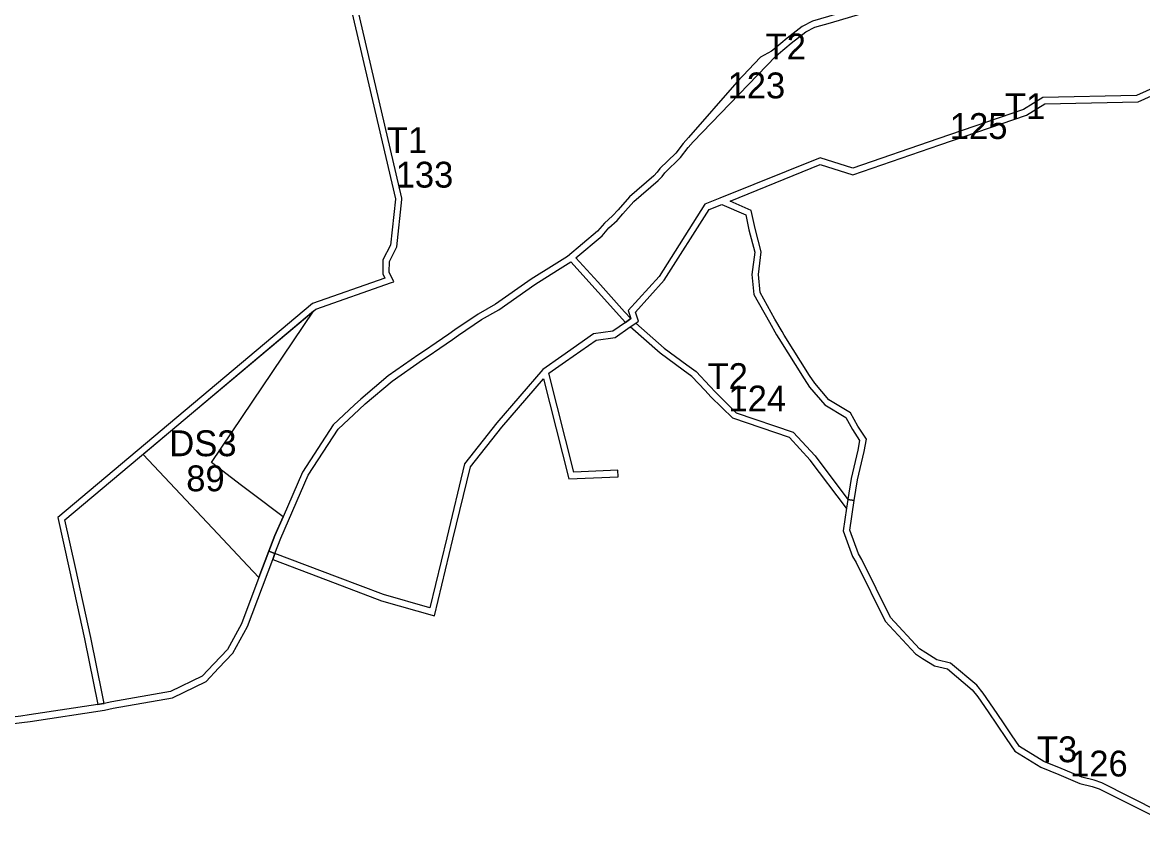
# Model space of a CAD drawing. Extents: x -477001 to -465642, y -1158278 to -1150672.
# Drawn here: x -469997 to -469477, y -1153800 to -1153423 of the extents above; entities that cross this region are included whole.
import ezdxf

# ---------------------------------------------------------------- set-up
doc = ezdxf.new("R2010")
doc.units = 0
for name, color, linetype in [('VPS_id', 7, 'Continuous'), ('VPS_n', 7, 'Continuous'), ('vyvlastneni_n', 7, 'Continuous')]:
    doc.layers.add(name, color=color, linetype=linetype)

msp = doc.modelspace()

# ---------------------------------------------------------------- linework, layer by layer
at = {"layer": 'VPS_n'}
for p, q in [((-469649.29, -1153436.68), (-469654.43, -1153439.34)), ((-469572.05, -1153477.33), (-469611.58, -1153490.89)), ((-469698.89, -1153493.04), (-469691.53, -1153485.91)), ((-469668.56, -1153506.2), (-469626.63, -1153489.26)), ((-469626.63, -1153489.26), (-469611.54, -1153494.04)), ((-469672.44, -1153507.77), (-469661.29, -1153512.67)), ((-469740.12, -1153532.5), (-469728, -1153522.3)), ((-469742.44, -1153534.42), (-469717.12, -1153562.51)), ((-469861.91, -1153557.27), (-469941.15, -1153623.82)), ((-469711.11, -1153561.96), (-469712.43, -1153557.85)), ((-469721.93, -1153569.54), (-469714.91, -1153564.62)), ((-469717.12, -1153562.51), (-469714.64, -1153560.78)), ((-469714.91, -1153564.62), (-469712.38, -1153562.85)), ((-469712.38, -1153562.85), (-469711.11, -1153561.96)), ((-469730.79, -1153570.76), (-469721.93, -1153569.54)), ((-469645.88, -1153570.06), (-469634.12, -1153588.78)), ((-469746.7, -1153578.23), (-469755.5, -1153584.39)), ((-469755.5, -1153584.39), (-469776.88, -1153609.23)), ((-469755.23, -1153588.67), (-469743.37, -1153635.1)), ((-469741.06, -1153632), (-469752.78, -1153586.14)), ((-469634.12, -1153588.78), (-469631.59, -1153592.55)), ((-469631.59, -1153592.55), (-469624.59, -1153600.78)), ((-469624.59, -1153600.78), (-469614.84, -1153606.66)), ((-469612.61, -1153604.5), (-469622.62, -1153598.46)), ((-469614.84, -1153606.66), (-469611.75, -1153612.19)), ((-469776.88, -1153609.23), (-469791.81, -1153628.18)), ((-469609.17, -1153621.89), (-469612.36, -1153635)), ((-469941.15, -1153623.82), (-469908.95, -1153658.04)), ((-469609.41, -1153635.58), (-469606.23, -1153622.5)), ((-469791.81, -1153628.18), (-469800.13, -1153662.51)), ((-469797.21, -1153663.22), (-469789.05, -1153629.52)), ((-469743.37, -1153635.1), (-469720.57, -1153634.19)), ((-469612.36, -1153635), (-469613.82, -1153644.71)), ((-469610.85, -1153645.16), (-469609.41, -1153635.58)), ((-469885.46, -1153645.71), (-469895.39, -1153638.21)), ((-469881.57, -1153648.65), (-469885.46, -1153645.71)), ((-469613.82, -1153644.71), (-469614.45, -1153648.86)), ((-469613.82, -1153644.71), (-469614.45, -1153648.86)), ((-469613.82, -1153644.71), (-469610.85, -1153645.16)), ((-469610.85, -1153645.16), (-469613.82, -1153644.71)), ((-469612.94, -1153659), (-469610.85, -1153645.16)), ((-469876.12, -1153652.76), (-469881.57, -1153648.65)), ((-469614.45, -1153648.86), (-469616.02, -1153659.31)), ((-469908.95, -1153658.04), (-469892.51, -1153675.5)), ((-469800.13, -1153662.51), (-469808.01, -1153695.03)), ((-469616.02, -1153659.31), (-469611.66, -1153671.22)), ((-469608.93, -1153669.95), (-469612.94, -1153659)), ((-469887.31, -1153681.03), (-469882.68, -1153668.8)), ((-469879.88, -1153669.86), (-469882.68, -1153668.8)), ((-469882.68, -1153668.8), (-469879.88, -1153669.86)), ((-469880.94, -1153672.67), (-469879.88, -1153669.86)), ((-469879.88, -1153669.86), (-469880.94, -1153672.67)), ((-469850.88, -1153680.84), (-469879.88, -1153669.86)), ((-469607.39, -1153672.66), (-469608.93, -1153669.95)), ((-469892.51, -1153675.5), (-469887.31, -1153681.03)), ((-469829.53, -1153688.92), (-469850.88, -1153680.84)), ((-469808.01, -1153695.03), (-469829.53, -1153688.92)), ((-469572.52, -1153719.17), (-469577.58, -1153716.01)), ((-469551.03, -1153734.63), (-469553.92, -1153730.99)), ((-469556.08, -1153733.09), (-469553.45, -1153736.41)), ((-469553.45, -1153736.41), (-469548.74, -1153743.32)), ((-469524.28, -1153769.01), (-469515.91, -1153772.5)), ((-469497.07, -1153779.12), (-469455.84, -1153799.88))]:
    msp.add_line(p, q, dxfattribs=at)
for points in [[(-469924.03, -1153225.48), (-469924.14, -1153237.9), (-469924.24, -1153248.64), (-469933.25, -1153282.8), (-469932.94, -1153293.65), (-469928.03, -1153316.16), (-469917.44, -1153355.79), (-469900.76, -1153373.26), (-469882.11, -1153382.51), (-469868.23, -1153389.4), (-469848.65, -1153399.12), (-469823.97, -1153505.24), (-469823.97, -1153505.33), (-469826.25, -1153526.64), (-469829.73, -1153533.5), (-469829.85, -1153539.94), (-469828.88, -1153541.96), (-469862.41, -1153553.77), (-469980.74, -1153653.15), (-469975.5, -1153676.95), (-469968.34, -1153709.45), (-469962.14, -1153739.93)], [(-469434.21, -1153343.98), (-469486.99, -1153367.69), (-469533.66, -1153388.67), (-469567.53, -1153403.78), (-469575.25, -1153407.62), (-469580.07, -1153409.16), (-469591.53, -1153411.76), (-469594.27, -1153412.12), (-469604.55, -1153415.16), (-469622.77, -1153420.54), (-469630.33, -1153422.61), (-469635.05, -1153425.16), (-469641.99, -1153430.58), (-469647.94, -1153435.55), (-469649.29, -1153436.68)], [(-469691.53, -1153485.91), (-469687.93, -1153481.41), (-469685.68, -1153478.75), (-469647.24, -1153438.88), (-469646.02, -1153437.85), (-469640.1, -1153432.91), (-469633.4, -1153427.68), (-469629.21, -1153425.41), (-469621.95, -1153423.43), (-469603.7, -1153418.04), (-469593.65, -1153415.06), (-469591, -1153414.72), (-469579.28, -1153412.06), (-469574.12, -1153410.41), (-469566.25, -1153406.49), (-469532.43, -1153391.41), (-469485.76, -1153370.43), (-469433.06, -1153346.75)], [(-469959.17, -1153739.45), (-469959.96, -1153735.58), (-469965.41, -1153708.83), (-469972.57, -1153676.31), (-469977.42, -1153654.27), (-469860.9, -1153556.42), (-469825.83, -1153544.07), (-469824.72, -1153543.68), (-469826.84, -1153539.28), (-469826.74, -1153534.24), (-469823.33, -1153527.51), (-469820.97, -1153505.51), (-469820.96, -1153504.92), (-469845.73, -1153398.41)], [(-469654.43, -1153439.34), (-469665.41, -1153451.06), (-469687.91, -1153476.74)], [(-469530.93, -1153466.4), (-469522.38, -1153461.1), (-469479.09, -1153460.16), (-469433.64, -1153439.78)], [(-469437.42, -1153438.18), (-469479.76, -1153457.17), (-469523.26, -1153458.12)], [(-469523.26, -1153458.12), (-469532.23, -1153463.67), (-469572.05, -1153477.33)], [(-469611.54, -1153494.04), (-469571.08, -1153480.17), (-469530.93, -1153466.4)], [(-469687.91, -1153476.74), (-469690.25, -1153479.5), (-469693.76, -1153483.89), (-469701.2, -1153491.11)], [(-469611.58, -1153490.89), (-469626.75, -1153486.08), (-469673.29, -1153504.87)], [(-469701.2, -1153491.11), (-469702.37, -1153492.85), (-469703.94, -1153494.48), (-469715.27, -1153504.3), (-469720.54, -1153510.21), (-469723.07, -1153513.06), (-469726.93, -1153516.52), (-469730.11, -1153520.15), (-469744.05, -1153531.89), (-469750.24, -1153535.79), (-469760.9, -1153542.49), (-469777.54, -1153554.12), (-469785.56, -1153558.69), (-469796.36, -1153566.04), (-469799.16, -1153567.94), (-469804.99, -1153571.96), (-469810.5, -1153575.75), (-469813.03, -1153577.5), (-469827.27, -1153587.39), (-469840.03, -1153598.14), (-469842.89, -1153600.81), (-469852.84, -1153610.11), (-469867.1, -1153632.03), (-469876.12, -1153652.76), (-469879.93, -1153661.52), (-469882.68, -1153668.8)], [(-469728, -1153522.3), (-469724.79, -1153518.63), (-469720.94, -1153515.18), (-469718.3, -1153512.2), (-469713.16, -1153506.44), (-469701.87, -1153496.66), (-469700.03, -1153494.74), (-469698.89, -1153493.04)], [(-469673.29, -1153504.87), (-469680.21, -1153507.67), (-469701.46, -1153541.16), (-469715.83, -1153557.09), (-469714.64, -1153560.78), (-469717.12, -1153562.51), (-469723.06, -1153566.66), (-469731.91, -1153567.88), (-469746.7, -1153578.23)], [(-469712.43, -1153557.85), (-469699.08, -1153543), (-469678.19, -1153510.09), (-469672.44, -1153507.77)], [(-469655.38, -1153540.33), (-469654.06, -1153529.73), (-469656.89, -1153518.94), (-469658.68, -1153510.54), (-469668.56, -1153506.2)], [(-469661.29, -1153512.67), (-469659.81, -1153519.63), (-469657.11, -1153529.93), (-469658.4, -1153540.3), (-469657.45, -1153549.65), (-469650.3, -1153562.44)], [(-469714.64, -1153560.78), (-469717.51, -1153557.59), (-469730, -1153543.73), (-469740.12, -1153532.5)], [(-469879.88, -1153669.86), (-469877.15, -1153662.65), (-469864.45, -1153633.46), (-469850.52, -1153612.05), (-469840.84, -1153603), (-469838.04, -1153600.39), (-469825.44, -1153589.77), (-469811.32, -1153579.97), (-469808.8, -1153578.22), (-469803.29, -1153574.43), (-469797.47, -1153570.42), (-469794.67, -1153568.52), (-469783.97, -1153561.24), (-469775.93, -1153556.66), (-469759.24, -1153544.99), (-469748.64, -1153538.33), (-469742.44, -1153534.42)], [(-469647.68, -1153560.97), (-469654.53, -1153548.73), (-469655.38, -1153540.33)], [(-469895.39, -1153638.21), (-469909.36, -1153627.65), (-469861.91, -1153557.27)], [(-469714.91, -1153564.62), (-469712.38, -1153562.85), (-469699.12, -1153574.55), (-469688.6, -1153582.22), (-469684.29, -1153585.35), (-469677.99, -1153592.12), (-469675.35, -1153594.94), (-469665.67, -1153604.45), (-469639.22, -1153613.46), (-469629.05, -1153624.54), (-469613.82, -1153644.71)], [(-469614.45, -1153648.86), (-469631.36, -1153626.46), (-469640.91, -1153616.05), (-469667.28, -1153607.07), (-469677.5, -1153597.04), (-469680.18, -1153594.17), (-469686.29, -1153587.61), (-469690.37, -1153584.64), (-469701, -1153576.89), (-469714.91, -1153564.62)], [(-469650.3, -1153562.44), (-469646.98, -1153568.35), (-469645.88, -1153570.06)], [(-469631.6, -1153587.15), (-469643.35, -1153568.45), (-469644.41, -1153566.8), (-469647.68, -1153560.97)], [(-469752.78, -1153586.14), (-469744.98, -1153580.69), (-469730.79, -1153570.76)], [(-469789.05, -1153629.52), (-469774.56, -1153611.14), (-469755.23, -1153588.67)], [(-469622.62, -1153598.46), (-469629.19, -1153590.74), (-469631.6, -1153587.15)], [(-469606.23, -1153622.5), (-469605.25, -1153616.7), (-469609.18, -1153610.64), (-469612.61, -1153604.5)], [(-469611.75, -1153612.19), (-469608.4, -1153617.35), (-469609.17, -1153621.89)], [(-469720.57, -1153634.19), (-469720.69, -1153631.19), (-469741.06, -1153632)], [(-469882.68, -1153668.8), (-469879.93, -1153661.52), (-469876.12, -1153652.76)], [(-469880.94, -1153672.67), (-469851.94, -1153683.65), (-469830.47, -1153691.77), (-469805.82, -1153698.77), (-469797.21, -1153663.22)], [(-469882.68, -1153668.8), (-469887.31, -1153681.03), (-469895.41, -1153702.45), (-469901.92, -1153714.36), (-469908.25, -1153721.08), (-469913.7, -1153726.86), (-469928.34, -1153733.94), (-469955.61, -1153738.69), (-469959.17, -1153739.45)], [(-470144.94, -1153792.24), (-470140.23, -1153791.32), (-470129.3, -1153787.64), (-470115.74, -1153783.08), (-470108.03, -1153780.1), (-470091.01, -1153773.14), (-470070.47, -1153764.33), (-470057.45, -1153759.75), (-470035.04, -1153753.64), (-470031.12, -1153752.97), (-470015.72, -1153750.56), (-469997.47, -1153748.33), (-469993.57, -1153747.76), (-469959.11, -1153742.5), (-469955.04, -1153741.64), (-469927.41, -1153736.82), (-469911.9, -1153729.32), (-469906.07, -1153723.14), (-469899.47, -1153716.14), (-469892.68, -1153703.71), (-469880.94, -1153672.67)], [(-469611.66, -1153671.22), (-469610.04, -1153674.07), (-469596.54, -1153701.21), (-469582.45, -1153716.49)], [(-469577.58, -1153716.01), (-469580.51, -1153714.16), (-469594.04, -1153699.49), (-469607.39, -1153672.66)], [(-469582.45, -1153716.49), (-469579.18, -1153718.55), (-469573.69, -1153721.97), (-469567.54, -1153723.44), (-469556.08, -1153733.09)], [(-469553.92, -1153730.99), (-469566.15, -1153720.69), (-469572.52, -1153719.17)], [(-469541.89, -1153748.05), (-469546.26, -1153741.63), (-469551.03, -1153734.63)], [(-469962.14, -1153739.93), (-469994.02, -1153744.79), (-469997.87, -1153745.36), (-470016.13, -1153747.59), (-470031.6, -1153750.01), (-470035.69, -1153750.71), (-470058.34, -1153756.88), (-470063.02, -1153758.53)], [(-469959.17, -1153739.45), (-469959.65, -1153739.55), (-469962.14, -1153739.93)], [(-469962.14, -1153739.93), (-469959.65, -1153739.55), (-469959.17, -1153739.45)], [(-469548.74, -1153743.32), (-469540.32, -1153755.69), (-469536.25, -1153761.66), (-469524.28, -1153769.01)], [(-469522.91, -1153766.33), (-469534.13, -1153759.44), (-469537.84, -1153754), (-469541.89, -1153748.05)], [(-469505.2, -1153773.71), (-469514.76, -1153769.73), (-469522.91, -1153766.33)], [(-469515.91, -1153772.5), (-469506.13, -1153776.57), (-469500.38, -1153777.95), (-469497.07, -1153779.12)], [(-469469.36, -1153789.71), (-469495.89, -1153776.35), (-469499.53, -1153775.07), (-469505.2, -1153773.71)]]:
    msp.add_lwpolyline(points, dxfattribs=at)
at = {"layer": 'vyvlastneni_n'}
for p, q in [((-469649.29, -1153436.68), (-469654.43, -1153439.34)), ((-469572.05, -1153477.33), (-469611.58, -1153490.89)), ((-469698.89, -1153493.04), (-469691.53, -1153485.91)), ((-469668.56, -1153506.2), (-469626.63, -1153489.26)), ((-469626.63, -1153489.26), (-469611.54, -1153494.04)), ((-469672.44, -1153507.77), (-469661.29, -1153512.67)), ((-469740.12, -1153532.5), (-469728, -1153522.3)), ((-469742.44, -1153534.42), (-469717.12, -1153562.51)), ((-469861.91, -1153557.27), (-469941.15, -1153623.82)), ((-469711.11, -1153561.96), (-469712.43, -1153557.85)), ((-469721.93, -1153569.54), (-469714.91, -1153564.62)), ((-469717.12, -1153562.51), (-469714.64, -1153560.78)), ((-469714.91, -1153564.62), (-469712.38, -1153562.85)), ((-469712.38, -1153562.85), (-469711.11, -1153561.96)), ((-469730.79, -1153570.76), (-469721.93, -1153569.54)), ((-469645.88, -1153570.06), (-469634.12, -1153588.78)), ((-469746.7, -1153578.23), (-469755.5, -1153584.39)), ((-469755.5, -1153584.39), (-469776.88, -1153609.23)), ((-469755.23, -1153588.67), (-469743.37, -1153635.1)), ((-469741.06, -1153632), (-469752.78, -1153586.14)), ((-469634.12, -1153588.78), (-469631.59, -1153592.55)), ((-469631.59, -1153592.55), (-469624.59, -1153600.78)), ((-469624.59, -1153600.78), (-469614.84, -1153606.66)), ((-469612.61, -1153604.5), (-469622.62, -1153598.46)), ((-469614.84, -1153606.66), (-469611.75, -1153612.19)), ((-469776.88, -1153609.23), (-469791.81, -1153628.18)), ((-469609.17, -1153621.89), (-469612.36, -1153635)), ((-469941.15, -1153623.82), (-469908.95, -1153658.04)), ((-469609.41, -1153635.58), (-469606.23, -1153622.5)), ((-469791.81, -1153628.18), (-469800.13, -1153662.51)), ((-469797.21, -1153663.22), (-469789.05, -1153629.52)), ((-469743.37, -1153635.1), (-469720.57, -1153634.19)), ((-469612.36, -1153635), (-469613.82, -1153644.71)), ((-469610.85, -1153645.16), (-469609.41, -1153635.58)), ((-469885.46, -1153645.71), (-469895.39, -1153638.21)), ((-469881.57, -1153648.65), (-469885.46, -1153645.71)), ((-469613.82, -1153644.71), (-469614.45, -1153648.86)), ((-469613.82, -1153644.71), (-469614.45, -1153648.86)), ((-469613.82, -1153644.71), (-469610.85, -1153645.16)), ((-469610.85, -1153645.16), (-469613.82, -1153644.71)), ((-469612.94, -1153659), (-469610.85, -1153645.16)), ((-469876.12, -1153652.76), (-469881.57, -1153648.65)), ((-469614.45, -1153648.86), (-469616.02, -1153659.31)), ((-469908.95, -1153658.04), (-469892.51, -1153675.5)), ((-469800.13, -1153662.51), (-469808.01, -1153695.03)), ((-469616.02, -1153659.31), (-469611.66, -1153671.22)), ((-469608.93, -1153669.95), (-469612.94, -1153659)), ((-469887.31, -1153681.03), (-469882.68, -1153668.8)), ((-469879.88, -1153669.86), (-469882.68, -1153668.8)), ((-469882.68, -1153668.8), (-469879.88, -1153669.86)), ((-469880.94, -1153672.67), (-469879.88, -1153669.86)), ((-469879.88, -1153669.86), (-469880.94, -1153672.67)), ((-469850.88, -1153680.84), (-469879.88, -1153669.86)), ((-469607.39, -1153672.66), (-469608.93, -1153669.95)), ((-469892.51, -1153675.5), (-469887.31, -1153681.03)), ((-469829.53, -1153688.92), (-469850.88, -1153680.84)), ((-469808.01, -1153695.03), (-469829.53, -1153688.92)), ((-469572.52, -1153719.17), (-469577.58, -1153716.01)), ((-469551.03, -1153734.63), (-469553.92, -1153730.99)), ((-469556.08, -1153733.09), (-469553.45, -1153736.41)), ((-469553.45, -1153736.41), (-469548.74, -1153743.32)), ((-469524.28, -1153769.01), (-469515.91, -1153772.5)), ((-469497.07, -1153779.12), (-469455.84, -1153799.88))]:
    msp.add_line(p, q, dxfattribs=at)
for points in [[(-469924.03, -1153225.48), (-469924.14, -1153237.9), (-469924.24, -1153248.64), (-469933.25, -1153282.8), (-469932.94, -1153293.65), (-469928.03, -1153316.16), (-469917.44, -1153355.79), (-469900.76, -1153373.26), (-469882.11, -1153382.51), (-469868.23, -1153389.4), (-469848.65, -1153399.12), (-469823.97, -1153505.24), (-469823.97, -1153505.33), (-469826.25, -1153526.64), (-469829.73, -1153533.5), (-469829.85, -1153539.94), (-469828.88, -1153541.96), (-469862.41, -1153553.77), (-469980.74, -1153653.15), (-469975.5, -1153676.95), (-469968.34, -1153709.45), (-469962.14, -1153739.93)], [(-469434.21, -1153343.98), (-469486.99, -1153367.69), (-469533.66, -1153388.67), (-469567.53, -1153403.78), (-469575.25, -1153407.62), (-469580.07, -1153409.16), (-469591.53, -1153411.76), (-469594.27, -1153412.12), (-469604.55, -1153415.16), (-469622.77, -1153420.54), (-469630.33, -1153422.61), (-469635.05, -1153425.16), (-469641.99, -1153430.58), (-469647.94, -1153435.55), (-469649.29, -1153436.68)], [(-469691.53, -1153485.91), (-469687.93, -1153481.41), (-469685.68, -1153478.75), (-469647.24, -1153438.88), (-469646.02, -1153437.85), (-469640.1, -1153432.91), (-469633.4, -1153427.68), (-469629.21, -1153425.41), (-469621.95, -1153423.43), (-469603.7, -1153418.04), (-469593.65, -1153415.06), (-469591, -1153414.72), (-469579.28, -1153412.06), (-469574.12, -1153410.41), (-469566.25, -1153406.49), (-469532.43, -1153391.41), (-469485.76, -1153370.43), (-469433.06, -1153346.75)], [(-469959.17, -1153739.45), (-469959.96, -1153735.58), (-469965.41, -1153708.83), (-469972.57, -1153676.31), (-469977.42, -1153654.27), (-469860.9, -1153556.42), (-469825.83, -1153544.07), (-469824.72, -1153543.68), (-469826.84, -1153539.28), (-469826.74, -1153534.24), (-469823.33, -1153527.51), (-469820.97, -1153505.51), (-469820.96, -1153504.92), (-469845.73, -1153398.41)], [(-469654.43, -1153439.34), (-469665.41, -1153451.06), (-469687.91, -1153476.74)], [(-469530.93, -1153466.4), (-469522.38, -1153461.1), (-469479.09, -1153460.16), (-469433.64, -1153439.78)], [(-469437.42, -1153438.18), (-469479.76, -1153457.17), (-469523.26, -1153458.12)], [(-469523.26, -1153458.12), (-469532.23, -1153463.67), (-469572.05, -1153477.33)], [(-469611.54, -1153494.04), (-469571.08, -1153480.17), (-469530.93, -1153466.4)], [(-469687.91, -1153476.74), (-469690.25, -1153479.5), (-469693.76, -1153483.89), (-469701.2, -1153491.11)], [(-469611.58, -1153490.89), (-469626.75, -1153486.08), (-469673.29, -1153504.87)], [(-469701.2, -1153491.11), (-469702.37, -1153492.85), (-469703.94, -1153494.48), (-469715.27, -1153504.3), (-469720.54, -1153510.21), (-469723.07, -1153513.06), (-469726.93, -1153516.52), (-469730.11, -1153520.15), (-469744.05, -1153531.89), (-469750.24, -1153535.79), (-469760.9, -1153542.49), (-469777.54, -1153554.12), (-469785.56, -1153558.69), (-469796.36, -1153566.04), (-469799.16, -1153567.94), (-469804.99, -1153571.96), (-469810.5, -1153575.75), (-469813.03, -1153577.5), (-469827.27, -1153587.39), (-469840.03, -1153598.14), (-469842.89, -1153600.81), (-469852.84, -1153610.11), (-469867.1, -1153632.03), (-469876.12, -1153652.76), (-469879.93, -1153661.52), (-469882.68, -1153668.8)], [(-469728, -1153522.3), (-469724.79, -1153518.63), (-469720.94, -1153515.18), (-469718.3, -1153512.2), (-469713.16, -1153506.44), (-469701.87, -1153496.66), (-469700.03, -1153494.74), (-469698.89, -1153493.04)], [(-469673.29, -1153504.87), (-469680.21, -1153507.67), (-469701.46, -1153541.16), (-469715.83, -1153557.09), (-469714.64, -1153560.78), (-469717.12, -1153562.51), (-469723.06, -1153566.66), (-469731.91, -1153567.88), (-469746.7, -1153578.23)], [(-469712.43, -1153557.85), (-469699.08, -1153543), (-469678.19, -1153510.09), (-469672.44, -1153507.77)], [(-469655.38, -1153540.33), (-469654.06, -1153529.73), (-469656.89, -1153518.94), (-469658.68, -1153510.54), (-469668.56, -1153506.2)], [(-469661.29, -1153512.67), (-469659.81, -1153519.63), (-469657.11, -1153529.93), (-469658.4, -1153540.3), (-469657.45, -1153549.65), (-469650.3, -1153562.44)], [(-469714.64, -1153560.78), (-469717.51, -1153557.59), (-469730, -1153543.73), (-469740.12, -1153532.5)], [(-469879.88, -1153669.86), (-469877.15, -1153662.65), (-469864.45, -1153633.46), (-469850.52, -1153612.05), (-469840.84, -1153603), (-469838.04, -1153600.39), (-469825.44, -1153589.77), (-469811.32, -1153579.97), (-469808.8, -1153578.22), (-469803.29, -1153574.43), (-469797.47, -1153570.42), (-469794.67, -1153568.52), (-469783.97, -1153561.24), (-469775.93, -1153556.66), (-469759.24, -1153544.99), (-469748.64, -1153538.33), (-469742.44, -1153534.42)], [(-469647.68, -1153560.97), (-469654.53, -1153548.73), (-469655.38, -1153540.33)], [(-469895.39, -1153638.21), (-469909.36, -1153627.65), (-469861.91, -1153557.27)], [(-469714.91, -1153564.62), (-469712.38, -1153562.85), (-469699.12, -1153574.55), (-469688.6, -1153582.22), (-469684.29, -1153585.35), (-469677.99, -1153592.12), (-469675.35, -1153594.94), (-469665.67, -1153604.45), (-469639.22, -1153613.46), (-469629.05, -1153624.54), (-469613.82, -1153644.71)], [(-469614.45, -1153648.86), (-469631.36, -1153626.46), (-469640.91, -1153616.05), (-469667.28, -1153607.07), (-469677.5, -1153597.04), (-469680.18, -1153594.17), (-469686.29, -1153587.61), (-469690.37, -1153584.64), (-469701, -1153576.89), (-469714.91, -1153564.62)], [(-469650.3, -1153562.44), (-469646.98, -1153568.35), (-469645.88, -1153570.06)], [(-469631.6, -1153587.15), (-469643.35, -1153568.45), (-469644.41, -1153566.8), (-469647.68, -1153560.97)], [(-469752.78, -1153586.14), (-469744.98, -1153580.69), (-469730.79, -1153570.76)], [(-469789.05, -1153629.52), (-469774.56, -1153611.14), (-469755.23, -1153588.67)], [(-469622.62, -1153598.46), (-469629.19, -1153590.74), (-469631.6, -1153587.15)], [(-469606.23, -1153622.5), (-469605.25, -1153616.7), (-469609.18, -1153610.64), (-469612.61, -1153604.5)], [(-469611.75, -1153612.19), (-469608.4, -1153617.35), (-469609.17, -1153621.89)], [(-469720.57, -1153634.19), (-469720.69, -1153631.19), (-469741.06, -1153632)], [(-469882.68, -1153668.8), (-469879.93, -1153661.52), (-469876.12, -1153652.76)], [(-469880.94, -1153672.67), (-469851.94, -1153683.65), (-469830.47, -1153691.77), (-469805.82, -1153698.77), (-469797.21, -1153663.22)], [(-469882.68, -1153668.8), (-469887.31, -1153681.03), (-469895.41, -1153702.45), (-469901.92, -1153714.36), (-469908.25, -1153721.08), (-469913.7, -1153726.86), (-469928.34, -1153733.94), (-469955.61, -1153738.69), (-469959.17, -1153739.45)], [(-470144.94, -1153792.24), (-470140.23, -1153791.32), (-470129.3, -1153787.64), (-470115.74, -1153783.08), (-470108.03, -1153780.1), (-470091.01, -1153773.14), (-470070.47, -1153764.33), (-470057.45, -1153759.75), (-470035.04, -1153753.64), (-470031.12, -1153752.97), (-470015.72, -1153750.56), (-469997.47, -1153748.33), (-469993.57, -1153747.76), (-469959.11, -1153742.5), (-469955.04, -1153741.64), (-469927.41, -1153736.82), (-469911.9, -1153729.32), (-469906.07, -1153723.14), (-469899.47, -1153716.14), (-469892.68, -1153703.71), (-469880.94, -1153672.67)], [(-469611.66, -1153671.22), (-469610.04, -1153674.07), (-469596.54, -1153701.21), (-469582.45, -1153716.49)], [(-469577.58, -1153716.01), (-469580.51, -1153714.16), (-469594.04, -1153699.49), (-469607.39, -1153672.66)], [(-469582.45, -1153716.49), (-469579.18, -1153718.55), (-469573.69, -1153721.97), (-469567.54, -1153723.44), (-469556.08, -1153733.09)], [(-469553.92, -1153730.99), (-469566.15, -1153720.69), (-469572.52, -1153719.17)], [(-469541.89, -1153748.05), (-469546.26, -1153741.63), (-469551.03, -1153734.63)], [(-469962.14, -1153739.93), (-469994.02, -1153744.79), (-469997.87, -1153745.36), (-470016.13, -1153747.59), (-470031.6, -1153750.01), (-470035.69, -1153750.71), (-470058.34, -1153756.88), (-470063.02, -1153758.53)], [(-469959.17, -1153739.45), (-469959.65, -1153739.55), (-469962.14, -1153739.93)], [(-469962.14, -1153739.93), (-469959.65, -1153739.55), (-469959.17, -1153739.45)], [(-469548.74, -1153743.32), (-469540.32, -1153755.69), (-469536.25, -1153761.66), (-469524.28, -1153769.01)], [(-469522.91, -1153766.33), (-469534.13, -1153759.44), (-469537.84, -1153754), (-469541.89, -1153748.05)], [(-469505.2, -1153773.71), (-469514.76, -1153769.73), (-469522.91, -1153766.33)], [(-469515.91, -1153772.5), (-469506.13, -1153776.57), (-469500.38, -1153777.95), (-469497.07, -1153779.12)], [(-469469.36, -1153789.71), (-469495.89, -1153776.35), (-469499.53, -1153775.07), (-469505.2, -1153773.71)]]:
    msp.add_lwpolyline(points, dxfattribs=at)

# ---------------------------------------------------------------- texts
at = {"layer": 'VPS_id'}
for s, p in [('123', (-469669.71, -1153458.51)), ('125', (-469566.49, -1153477.38)), ('133', (-469823.84, -1153499.95)), ('124', (-469669.27, -1153603.89)), ('89', (-469921.08, -1153640.95)), ('126', (-469510.67, -1153773.37))]:
    msp.add_text(s, height=12, dxfattribs=at).set_placement(p)
at = {"layer": 'VPS_n'}
for s, p in [('T2', (-469652.03, -1153440.45)), ('T1', (-469540.93, -1153468.15)), ('T1', (-469827.93, -1153483.91)), ('T2', (-469678.99, -1153593.48)), ('DS3', (-469928.94, -1153624.66)), ('T3', (-469526.08, -1153766.74))]:
    msp.add_text(s, height=12, dxfattribs=at).set_placement(p)

doc.saveas('drawing.dxf')
